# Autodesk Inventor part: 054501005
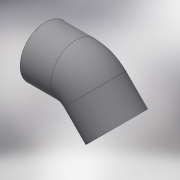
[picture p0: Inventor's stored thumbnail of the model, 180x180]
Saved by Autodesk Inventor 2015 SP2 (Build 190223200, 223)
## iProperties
Created: 2017-10
Part Number: 054501005
Material: Generic
Description: PLASSON THREADED 45° ELBOW HF 1/2"
Document SubType Name: Modeling
Designer: KIM
Mass: 11.7217 g
Surface Area: 66.5443 cm^2
Volume: 11.7217 cm^3
Density: 1 g/cm^3
Appearance: Default
Author: KIM
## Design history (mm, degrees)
derived "054501.ipt"
feature "Solid1::054501.ipt"
tag "TaggingFeature1"
body "Solid1"
other parameters: "d7" = 0.18631, "d9" = 26, "d13" = 135 deg, "d18" = 5, "d19" = 45 deg, "d20" = 18.631, "d21" = 17, "d22" = 0, "d28" = 22, "d29" = 18.631, "d30" = 17, "d31" = 0, "d32" = 16.7679, "d33" = 45 deg, "E_" = 26, "lt_" = 17, "Z_" = 5, "G_" = 18.631
